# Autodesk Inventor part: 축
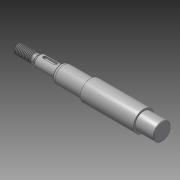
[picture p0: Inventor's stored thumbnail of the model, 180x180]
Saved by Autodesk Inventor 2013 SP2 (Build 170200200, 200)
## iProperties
Created: 2015-11
Part Number: 축
Material: 강철, 연강
Document SubType Name: Modeling
Designer: mduedu
Density: 1 g/cm^3
Author: mduedu
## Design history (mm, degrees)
sketch "스케치1"
  geometry: L1 (-86, 0)-(86, 0); L2 (-86, 0)-(-86, 4); L3 (-86, 4)-(-70.732, 4); L4 (-70.732, 4)-(-69, 3); L5 (-69, 3)-(-67, 3); L6 (-67, 3)-(-67, 5); L7 (-67, 5)-(-49, 5); L8 (-49, 5)-(-49, 6.55); L9 (-47.355, 7.5)-(-23, 7.5); L10 (-23, 7.5)-(-23, 9); L11 (0, 0)-(0, 9); L12 (86, 4)-(70.732, 4); L13 (70.732, 4)-(69, 3); L14 (69, 3)-(67, 3); L15 (67, 3)-(67, 5); L16 (67, 5)-(49, 5); L17 (23, 7.5)-(23, 9); L18 (86, 0)-(86, 4); L19 (-23, 9)-(23, 9); L20 (-49, 6.55)-(-47.355, 7.5); L21 (47.355, 7.5)-(23, 7.5); L22 (49, 6.55)-(47.355, 7.5); L23 (49, 5)-(49, 6.55); 1 further point
  constraints: 46 end point, 10 symmetric about line, 6 perpendicular, 5 parallel, 2 midpoint, 1 coincident, 1 horizontal
  dimensions: "d0" = 172 distance of L1.start L1.end (derived); "d1" = 8 diameter of L3 L1; "d2" = 30 deg angle of L4 L5; "d3" = 6 diameter of L5 L1; "d4" = 10 diameter of L7 L1; "d5" = 15 diameter of L9 L1; "d6" = 18 diameter of L19 L1; "d8" = 18 distance of L6.end L7.end; "d9" = 46 distance of L10.end L17.end; "d10" = 2 distance of L4.end L5.end; "d11" = 17 distance from line of L4.end L2; "d16" = 13.1 diameter of L8.end L1; "d17" = 30 deg angle of L20 L9; "d18" = 26 distance between parallel lines of L10 L8
revolve "회전1" sketch "스케치1" stored, may be unused: angle "d12" = 90 deg
chamfer "모따기1" distance "d13" = 0.5; stored, may be unused: second distance "d14" = 2, angle "d15" = 45 deg
fillet "모깎기1" dims "d19" = 4, "d20" = 0.5
node "작업 평면1"
sketch "스케치2" dims "d23" = 12
  geometry: L1 (-4.5, 1.5)-(4.5, 1.5); L2 (4.5, 1.5)-(4.5, -1.5); L3 (4.5, -1.5)-(-4.5, -1.5); L4 (-4.5, -1.5)-(-4.5, 1.5); L5 (-9, -4.5)-(-9, 4.5) reference; 3 further points
  constraints: 8 end point, 2 midpoint, 2 parallel, 2 vertical alignment, 1 horizontal, 1 perpendicular, 4 other
  dimensions: "d21" = 3 distance between parallel lines of L3 L1; "d24" = 3 dimension on L5
extrude "돌출1" cut sketch "스케치2" distance "d25" = 1.8; taper "d26" = 0 deg
feature "스레드1" dims "d27" = 10, "d28" = 0
feature "스레드2" dims "d29" = 10, "d30" = 0
chamfer "모따기2" distance "d31" = 0.5; stored, may be unused: second distance "d32" = 2, angle "d33" = 45 deg
node "작업 평면2"
sketch "스케치3"
  geometry: C1 r 7.5 at (0, 0) reference; 1 further point
extrude "돌출2" cut sketch "스케치3" stored distance "d36" = 10; taper "d37" = 0 deg
chamfer "모따기3" distance "d38" = 0.5; stored, may be unused: second distance "d39" = 2, angle "d40" = 45 deg
fillet "모깎기3" dims "d41" = 0.6
node "솔리드1"
mirror "대칭1"
node "절단 모서리 투영1"
other parameters: "d35" = 16
